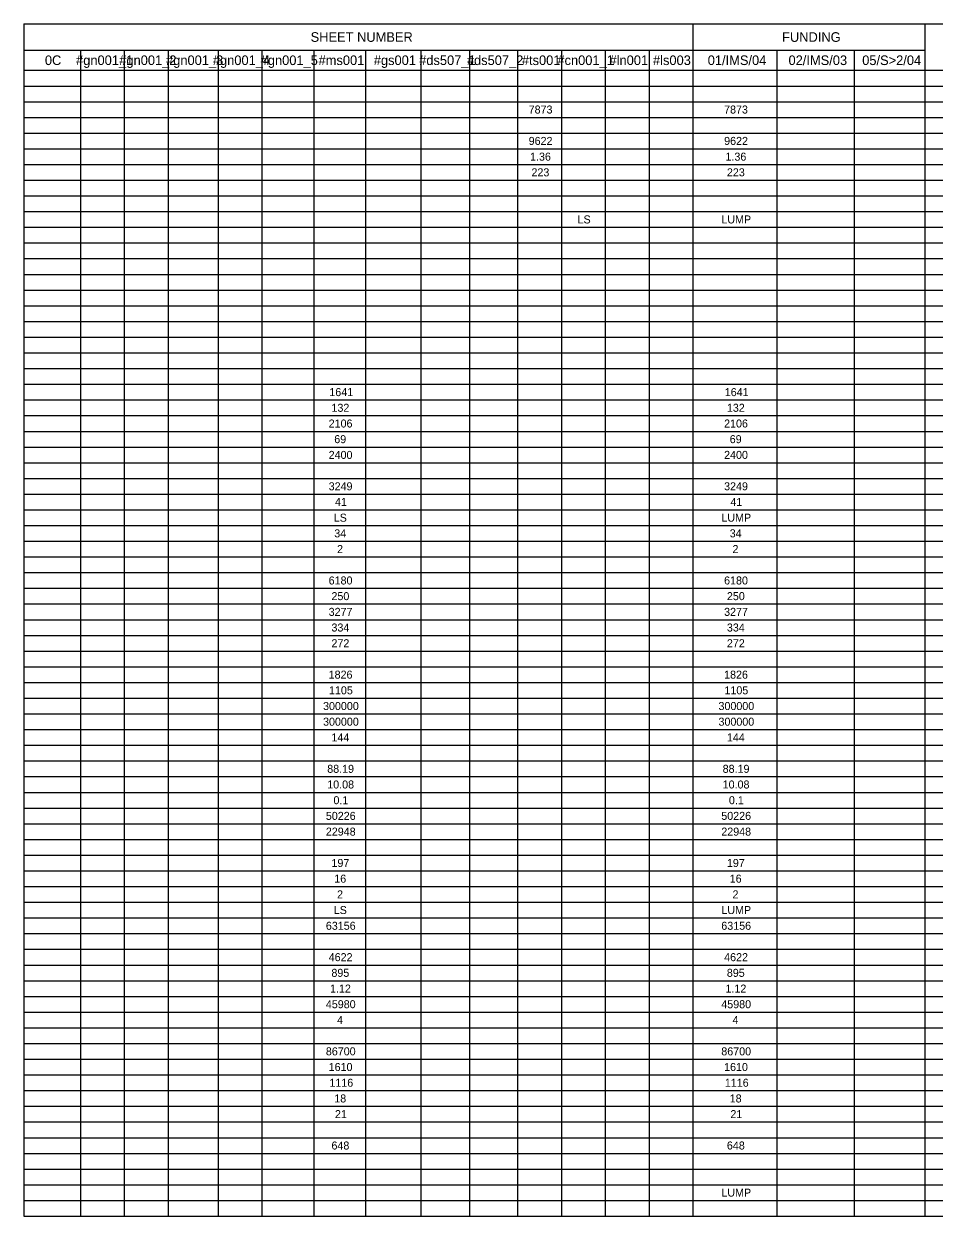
# Model space of a CAD drawing. Extents: x -542 to 295, y -281 to 32.
# Drawn here: x -541.71 to -525.79, y -130.44 to -109.59 of the extents above; entities that cross this region are included whole.
import ezdxf

# ---------------------------------------------------------------- set-up
doc = ezdxf.new("R2010")
doc.units = 0
doc.layers.add('SH_Data', color=7, linetype='Continuous')
doc.layers.add('SH_Text', color=7, linetype='Continuous')

msp = doc.modelspace()

# ---------------------------------------------------------------- linework, layer by layer
at = {"layer": 'SH_Data'}
for p, q in [((-541.706, -109.593), (-511.206, -109.593)), ((-541.706, -109.593), (-541.706, -130.444)), ((-530.01, -109.593), (-530.01, -130.444)), ((-525.956, -109.593), (-525.956, -130.444)), ((-541.706, -110.054), (-525.956, -110.054)), ((-540.716, -110.054), (-540.716, -130.444)), ((-539.95, -110.054), (-539.95, -130.444)), ((-539.184, -110.054), (-539.184, -130.444)), ((-538.311, -110.054), (-538.311, -130.444)), ((-537.545, -110.054), (-537.545, -130.444)), ((-536.64, -110.054), (-536.64, -130.444)), ((-535.736, -110.054), (-535.736, -130.444)), ((-534.767, -110.054), (-534.767, -130.444)), ((-533.916, -110.054), (-533.916, -130.444)), ((-533.075, -110.054), (-533.075, -130.444)), ((-532.309, -110.054), (-532.309, -130.444)), ((-531.543, -110.054), (-531.543, -130.444)), ((-530.776, -110.054), (-530.776, -130.444)), ((-528.542, -110.054), (-528.542, -130.444)), ((-527.19, -110.054), (-527.19, -130.444)), ((-541.706, -110.405), (-511.206, -110.405)), ((-541.706, -110.68), (-511.206, -110.68)), ((-541.706, -110.954), (-511.206, -110.954)), ((-541.706, -111.229), (-511.206, -111.229)), ((-541.706, -111.503), (-511.206, -111.503)), ((-541.706, -111.778), (-511.206, -111.778)), ((-541.706, -112.052), (-511.206, -112.052)), ((-541.706, -112.327), (-511.206, -112.327)), ((-541.706, -112.601), (-511.206, -112.601)), ((-541.706, -112.876), (-511.206, -112.876)), ((-541.706, -113.15), (-511.206, -113.15)), ((-541.706, -113.425), (-511.206, -113.425)), ((-541.706, -113.699), (-511.206, -113.699)), ((-541.706, -113.974), (-511.206, -113.974)), ((-541.706, -114.248), (-511.206, -114.248)), ((-541.706, -114.523), (-511.206, -114.523)), ((-541.706, -114.797), (-511.206, -114.797)), ((-541.706, -115.072), (-511.206, -115.072)), ((-541.706, -115.346), (-511.206, -115.346)), ((-541.706, -115.621), (-511.206, -115.621)), ((-541.706, -115.895), (-511.206, -115.895)), ((-541.706, -116.17), (-511.206, -116.17)), ((-541.706, -116.444), (-511.206, -116.444)), ((-541.706, -116.719), (-511.206, -116.719)), ((-541.706, -116.993), (-511.206, -116.993)), ((-541.706, -117.268), (-511.206, -117.268)), ((-541.706, -117.542), (-511.206, -117.542)), ((-541.706, -117.817), (-511.206, -117.817)), ((-541.706, -118.091), (-511.206, -118.091)), ((-541.706, -118.366), (-511.206, -118.366)), ((-541.706, -118.64), (-511.206, -118.64)), ((-541.706, -118.915), (-511.206, -118.915)), ((-541.706, -119.189), (-511.206, -119.189)), ((-541.706, -119.464), (-511.206, -119.464)), ((-541.706, -119.738), (-511.206, -119.738)), ((-541.706, -120.013), (-511.206, -120.013)), ((-541.706, -120.287), (-511.206, -120.287)), ((-541.706, -120.562), (-511.206, -120.562)), ((-541.706, -120.836), (-511.206, -120.836)), ((-541.706, -121.111), (-511.206, -121.111)), ((-541.706, -121.385), (-511.206, -121.385)), ((-541.706, -121.66), (-511.206, -121.66)), ((-541.706, -121.935), (-511.206, -121.935)), ((-541.706, -122.209), (-511.206, -122.209)), ((-541.706, -122.484), (-511.206, -122.484)), ((-541.706, -122.758), (-511.206, -122.758)), ((-541.706, -123.033), (-511.206, -123.033)), ((-541.706, -123.307), (-511.206, -123.307)), ((-541.706, -123.582), (-511.206, -123.582)), ((-541.706, -123.856), (-511.206, -123.856)), ((-541.706, -124.131), (-511.206, -124.131)), ((-541.706, -124.405), (-511.206, -124.405)), ((-541.706, -124.68), (-511.206, -124.68)), ((-541.706, -124.954), (-511.206, -124.954)), ((-541.706, -125.229), (-511.206, -125.229)), ((-541.706, -125.503), (-511.206, -125.503)), ((-541.706, -125.778), (-511.206, -125.778)), ((-541.706, -126.052), (-511.206, -126.052)), ((-541.706, -126.327), (-511.206, -126.327)), ((-541.706, -126.601), (-511.206, -126.601)), ((-541.706, -126.876), (-511.206, -126.876)), ((-541.706, -127.15), (-511.206, -127.15)), ((-541.706, -127.425), (-511.206, -127.425)), ((-541.706, -127.699), (-511.206, -127.699)), ((-541.706, -127.974), (-511.206, -127.974)), ((-541.706, -128.248), (-511.206, -128.248)), ((-541.706, -128.523), (-511.206, -128.523)), ((-541.706, -128.797), (-511.206, -128.797)), ((-541.706, -129.072), (-511.206, -129.072)), ((-541.706, -129.346), (-511.206, -129.346)), ((-541.706, -129.621), (-511.206, -129.621)), ((-541.706, -129.895), (-511.206, -129.895)), ((-541.706, -130.17), (-511.206, -130.17)), ((-541.706, -130.444), (-511.206, -130.444))]:
    msp.add_line(p, q, dxfattribs=at)

# ---------------------------------------------------------------- texts
at = {"layer": 'SH_Text'}
for s, height, p in [('SHEET NUMBER', 0.168, (-536.693, -109.907)), ('FUNDING', 0.168, (-528.452, -109.907)), ('0C', 0.168, (-541.338, -110.313)), ('#gn001_1', 0.168, (-540.793, -110.313)), ('#gn001_2', 0.168, (-540.038, -110.313)), ('#gn001_3', 0.168, (-539.22, -110.313)), ('#gn001_4', 0.168, (-538.402, -110.313)), ('#gn001_5', 0.168, (-537.566, -110.313)), ('#ms001', 0.168, (-536.554, -110.313)), ('#gs001', 0.168, (-535.589, -110.313)), ('#ds507_1', 0.168, (-534.796, -110.313)), ('#ds507_2', 0.168, (-533.962, -110.313)), ('#ts001', 0.168, (-533.001, -110.313)), ('#cn001_1', 0.168, (-532.38, -110.313)), ('#ln001', 0.168, (-531.469, -110.313)), ('#ls003', 0.168, (-530.709, -110.313)), ('01/IMS/04', 0.168, (-529.752, -110.313)), ('02/IMS/03', 0.168, (-528.34, -110.313)), ('05/S>2/04', 0.168, (-527.052, -110.313)), ('7873', 0.14, (-532.882, -111.161)), ('7873', 0.14, (-529.466, -111.161)), ('9622', 0.14, (-532.882, -111.71)), ('9622', 0.14, (-529.465, -111.71)), ('1.36', 0.14, (-532.858, -111.985)), ('1.36', 0.14, (-529.442, -111.985)), ('223', 0.14, (-532.833, -112.259)), ('223', 0.14, (-529.417, -112.259)), ('LS', 0.14, (-532.027, -113.083)), ('LUMP', 0.14, (-529.514, -113.083)), ('1641', 0.14, (-536.366, -116.103)), ('1641', 0.14, (-529.454, -116.103)), ('132', 0.14, (-536.329, -116.377)), ('132', 0.14, (-529.417, -116.377)), ('2106', 0.14, (-536.378, -116.652)), ('2106', 0.14, (-529.466, -116.652)), ('69', 0.14, (-536.28, -116.926)), ('69', 0.14, (-529.368, -116.926)), ('2400', 0.14, (-536.378, -117.201)), ('2400', 0.14, (-529.466, -117.201)), ('3249', 0.14, (-536.378, -117.75)), ('3249', 0.14, (-529.466, -117.75)), ('41', 0.14, (-536.268, -118.024)), ('41', 0.14, (-529.356, -118.024)), ('LS', 0.14, (-536.289, -118.299)), ('LUMP', 0.14, (-529.514, -118.299)), ('34', 0.14, (-536.28, -118.573)), ('34', 0.14, (-529.368, -118.573)), ('2', 0.14, (-536.231, -118.848)), ('2', 0.14, (-529.319, -118.848)), ('6180', 0.14, (-536.378, -119.397)), ('6180', 0.14, (-529.466, -119.397)), ('250', 0.14, (-536.329, -119.671)), ('250', 0.14, (-529.417, -119.671)), ('3277', 0.14, (-536.378, -119.946)), ('3277', 0.14, (-529.466, -119.946)), ('334', 0.14, (-536.329, -120.22)), ('334', 0.14, (-529.417, -120.22)), ('272', 0.14, (-536.329, -120.495)), ('272', 0.14, (-529.417, -120.495)), ('1826', 0.14, (-536.378, -121.044)), ('1826', 0.14, (-529.466, -121.044)), ('1105', 0.14, (-536.372, -121.318)), ('1105', 0.14, (-529.46, -121.318)), ('300000', 0.14, (-536.476, -121.593)), ('300000', 0.14, (-529.564, -121.593)), ('300000', 0.14, (-536.476, -121.867)), ('300000', 0.14, (-529.564, -121.867)), ('144', 0.14, (-536.329, -122.142)), ('144', 0.14, (-529.417, -122.142)), ('88.19', 0.14, (-536.403, -122.691)), ('88.19', 0.14, (-529.491, -122.691)), ('10.08', 0.14, (-536.403, -122.965)), ('10.08', 0.14, (-529.491, -122.965)), ('0.1', 0.14, (-536.294, -123.24)), ('0.1', 0.14, (-529.382, -123.24)), ('50226', 0.14, (-536.427, -123.514)), ('50226', 0.14, (-529.515, -123.514)), ('22948', 0.14, (-536.427, -123.789)), ('22948', 0.14, (-529.515, -123.789)), ('197', 0.14, (-536.329, -124.338)), ('197', 0.14, (-529.417, -124.338)), ('16', 0.14, (-536.28, -124.612)), ('16', 0.14, (-529.368, -124.612)), ('2', 0.14, (-536.231, -124.887)), ('2', 0.14, (-529.319, -124.887)), ('LS', 0.14, (-536.289, -125.161)), ('LUMP', 0.14, (-529.514, -125.161)), ('63156', 0.14, (-536.427, -125.436)), ('63156', 0.14, (-529.515, -125.436)), ('4622', 0.14, (-536.377, -125.985)), ('4622', 0.14, (-529.465, -125.985)), ('895', 0.14, (-536.33, -126.259)), ('895', 0.14, (-529.418, -126.259)), ('1.12', 0.14, (-536.354, -126.534)), ('1.12', 0.14, (-529.442, -126.534)), ('45980', 0.14, (-536.427, -126.808)), ('45980', 0.14, (-529.515, -126.808)), ('4', 0.14, (-536.231, -127.083)), ('4', 0.14, (-529.319, -127.083)), ('86700', 0.14, (-536.427, -127.632)), ('86700', 0.14, (-529.515, -127.632)), ('1610', 0.14, (-536.378, -127.906)), ('1610', 0.14, (-529.466, -127.906)), ('1116', 0.14, (-536.365, -128.181)), ('1116', 0.14, (-529.453, -128.181)), ('18', 0.14, (-536.28, -128.456)), ('18', 0.14, (-529.368, -128.456)), ('21', 0.14, (-536.268, -128.73)), ('21', 0.14, (-529.356, -128.73)), ('648', 0.14, (-536.329, -129.279)), ('648', 0.14, (-529.417, -129.279)), ('LUMP', 0.14, (-529.514, -130.103))]:
    msp.add_text(s, height=height, dxfattribs=at).set_placement(p)

doc.saveas('drawing.dxf')
